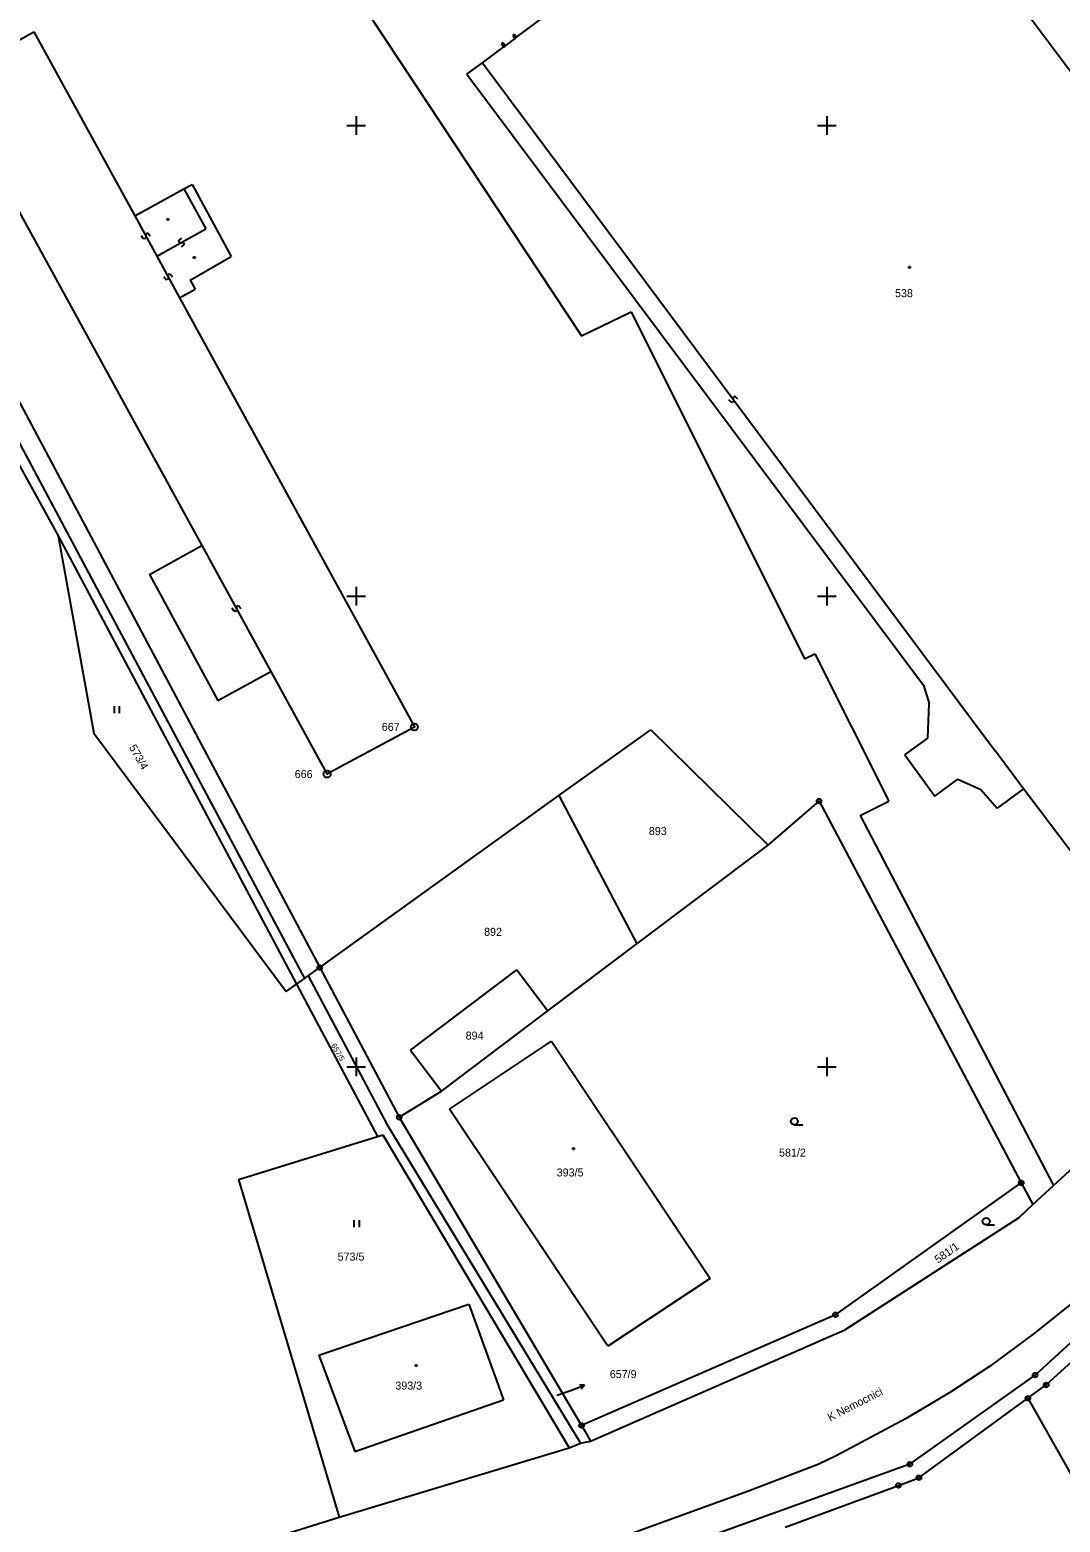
# Model space of a CAD drawing. Extents: x -493648 to -493033, y -1127718 to -1127026.
# Drawn here: x -493284.7 to -493175.2, y -1127598.4 to -1127439.8 of the extents above; entities that cross this region are included whole.
import ezdxf

# ---------------------------------------------------------------- set-up
doc = ezdxf.new("R2010")
doc.units = 0
doc.layers.add('katastrální mapa', color=7, linetype='Continuous')
doc.layers.add('síť', color=7, linetype='Continuous')

msp = doc.modelspace()

# ---------------------------------------------------------------- linework, layer by layer
at = {"layer": 'katastrální mapa'}
for p, q in [((-493232.95, -1127440.62), (-493201.08, -1127416.82)), ((-493254.36, -1127429.53), (-493226.07, -1127472.34)), ((-493182.89, -1127432.48), (-493156.39, -1127468.02)), ((-493293.46, -1127445.19), (-493284.22, -1127440.05)), ((-493284.22, -1127440.05), (-493273.51, -1127459.61)), ((-493233.34, -1127440.42), (-493233.19, -1127440.3)), ((-493233.34, -1127440.42), (-493233.1, -1127440.74)), ((-493233.19, -1127440.3), (-493232.95, -1127440.62)), ((-493233.1, -1127440.74), (-493232.95, -1127440.62)), ((-493236.57, -1127443.33), (-493234.3, -1127441.63)), ((-493234.54, -1127441.31), (-493234.38, -1127441.19)), ((-493234.54, -1127441.31), (-493234.3, -1127441.63)), ((-493234.38, -1127441.19), (-493234.14, -1127441.52)), ((-493234.3, -1127441.63), (-493234.14, -1127441.52)), ((-493234.14, -1127441.52), (-493233.1, -1127440.74)), ((-493238.25, -1127444.56), (-493236.57, -1127443.33)), ((-493236.57, -1127443.33), (-493183.28, -1127514.87)), ((-493293.46, -1127445.19), (-493266.37, -1127494.63)), ((-493238.25, -1127444.56), (-493189.73, -1127509.45)), ((-493268.3, -1127456.72), (-493267.42, -1127456.25)), ((-493267.42, -1127456.25), (-493263.27, -1127463.93)), ((-493273.51, -1127459.61), (-493268.3, -1127456.72)), ((-493268.3, -1127456.72), (-493265.97, -1127460.96)), ((-493273.51, -1127459.61), (-493271.17, -1127463.88)), ((-493271.17, -1127463.88), (-493265.97, -1127460.96)), ((-493270.07, -1127459.91), (-493269.92, -1127459.91)), ((-493270.07, -1127460.06), (-493270.07, -1127459.91)), ((-493269.92, -1127460.06), (-493270.07, -1127460.06)), ((-493269.92, -1127459.91), (-493269.92, -1127460.06)), ((-493272.6, -1127462), (-493272.81, -1127461.72)), ((-493272.46, -1127462.04), (-493272.6, -1127462)), ((-493272.38, -1127461.99), (-493272.46, -1127462.04)), ((-493272.34, -1127461.86), (-493272.38, -1127461.99)), ((-493272.3, -1127461.5), (-493272.34, -1127461.63)), ((-493272.34, -1127461.63), (-493272.34, -1127461.86)), ((-493272.22, -1127461.45), (-493272.3, -1127461.5)), ((-493272.08, -1127461.49), (-493272.22, -1127461.45)), ((-493271.87, -1127461.77), (-493272.08, -1127461.49)), ((-493268.83, -1127462.16), (-493268.87, -1127462.3)), ((-493268.87, -1127462.3), (-493268.82, -1127462.39)), ((-493268.55, -1127461.95), (-493268.83, -1127462.16)), ((-493268.82, -1127462.39), (-493268.68, -1127462.43)), ((-493268.68, -1127462.43), (-493268.46, -1127462.41)), ((-493268.31, -1127462.68), (-493268.59, -1127462.89)), ((-493268.46, -1127462.41), (-493268.32, -1127462.45)), ((-493268.32, -1127462.45), (-493268.27, -1127462.54)), ((-493268.27, -1127462.54), (-493268.31, -1127462.68)), ((-493271.17, -1127463.88), (-493268.75, -1127468.29)), ((-493267.62, -1127466.41), (-493263.27, -1127463.93)), ((-493267.26, -1127463.94), (-493267.11, -1127463.94)), ((-493267.26, -1127464.09), (-493267.26, -1127463.94)), ((-493267.11, -1127464.09), (-493267.26, -1127464.09)), ((-493267.11, -1127463.94), (-493267.11, -1127464.09)), ((-493269.92, -1127465.84), (-493269.96, -1127465.97)), ((-493269.96, -1127465.97), (-493269.96, -1127466.2)), ((-493269.84, -1127465.79), (-493269.92, -1127465.84)), ((-493269.7, -1127465.83), (-493269.84, -1127465.79)), ((-493269.49, -1127466.11), (-493269.7, -1127465.83)), ((-493191.3, -1127464.99), (-493191.15, -1127464.99)), ((-493191.3, -1127465.14), (-493191.3, -1127464.99)), ((-493191.15, -1127465.14), (-493191.3, -1127465.14)), ((-493191.15, -1127464.99), (-493191.15, -1127465.14)), ((-493270.22, -1127466.34), (-493270.43, -1127466.06)), ((-493270.08, -1127466.38), (-493270.22, -1127466.34)), ((-493270, -1127466.33), (-493270.08, -1127466.38)), ((-493269.96, -1127466.2), (-493270, -1127466.33)), ((-493268.75, -1127468.29), (-493267.09, -1127467.38)), ((-493267.62, -1127466.41), (-493267.09, -1127467.38)), ((-493295.49, -1127468.67), (-493281.65, -1127493.57)), ((-493268.75, -1127468.29), (-493243.81, -1127513.86)), ((-493226.07, -1127472.34), (-493220.77, -1127469.79)), ((-493220.77, -1127469.79), (-493202.35, -1127506.66)), ((-493287.7, -1127480.1), (-493255.49, -1127540.62)), ((-493285.95, -1127478.98), (-493253.86, -1127539.45)), ((-493210.15, -1127479.39), (-493210.4, -1127479.14)), ((-493210.01, -1127479.41), (-493210.15, -1127479.39)), ((-493209.93, -1127479.35), (-493210.01, -1127479.41)), ((-493209.92, -1127478.85), (-493209.94, -1127478.99)), ((-493209.94, -1127478.99), (-493209.91, -1127479.21)), ((-493209.91, -1127479.21), (-493209.93, -1127479.35)), ((-493209.84, -1127478.79), (-493209.92, -1127478.85)), ((-493209.7, -1127478.81), (-493209.84, -1127478.79)), ((-493209.45, -1127479.06), (-493209.7, -1127478.81)), ((-493281.65, -1127493.57), (-493277.86, -1127514.55)), ((-493281.65, -1127493.57), (-493256.33, -1127541.22)), ((-493175.91, -1127562.6), (-493102.04, -1127494.48)), ((-493271.96, -1127497.69), (-493266.37, -1127494.63)), ((-493266.37, -1127494.63), (-493259.05, -1127507.99)), ((-493271.96, -1127497.69), (-493264.7, -1127511.08)), ((-493262.97, -1127501.57), (-493263.18, -1127501.28)), ((-493262.83, -1127501.61), (-493262.97, -1127501.57)), ((-493262.75, -1127501.56), (-493262.83, -1127501.61)), ((-493262.71, -1127501.42), (-493262.75, -1127501.56)), ((-493262.67, -1127501.06), (-493262.71, -1127501.2)), ((-493262.71, -1127501.2), (-493262.71, -1127501.42)), ((-493262.59, -1127501.01), (-493262.67, -1127501.06)), ((-493262.45, -1127501.05), (-493262.59, -1127501.01)), ((-493262.24, -1127501.34), (-493262.45, -1127501.05)), ((-493202.35, -1127506.66), (-493201.28, -1127506.13)), ((-493201.28, -1127506.13), (-493193.41, -1127521.77)), ((-493264.7, -1127511.08), (-493259.05, -1127507.99)), ((-493259.05, -1127507.99), (-493253.09, -1127518.87)), ((-493189.73, -1127509.45), (-493189.11, -1127511.39)), ((-493275.68, -1127512.42), (-493275.68, -1127511.67)), ((-493275.18, -1127511.67), (-493275.18, -1127512.42)), ((-493189.28, -1127515.09), (-493189.11, -1127511.39)), ((-493177.87, -1127582.75), (-493098.97, -1127510.41)), ((-493277.86, -1127514.55), (-493257.43, -1127542.01)), ((-493253.09, -1127518.87), (-493243.81, -1127513.86)), ((-493228.45, -1127521.17), (-493218.7, -1127514.18)), ((-493218.7, -1127514.18), (-493206.22, -1127526.45)), ((-493191.72, -1127516.85), (-493189.28, -1127515.09)), ((-493183.28, -1127514.87), (-493182.09, -1127516.46)), ((-493179.09, -1127520.45), (-493182.09, -1127516.46)), ((-493191.72, -1127516.85), (-493188.53, -1127521.23)), ((-493188.53, -1127521.23), (-493186.09, -1127519.45)), ((-493186.09, -1127519.45), (-493183.62, -1127520.54)), ((-493253.86, -1127539.45), (-493228.45, -1127521.17)), ((-493228.45, -1127521.17), (-493220.16, -1127536.92)), ((-493183.62, -1127520.54), (-493181.9, -1127522.52)), ((-493179.09, -1127520.45), (-493181.9, -1127522.52)), ((-493170.1, -1127532.41), (-493179.09, -1127520.45)), ((-493206.22, -1127526.45), (-493200.81, -1127521.76)), ((-493200.81, -1127521.76), (-493179.34, -1127562.32)), ((-493196.45, -1127523.3), (-493193.41, -1127521.77)), ((-493196.45, -1127523.3), (-493175.91, -1127562.6)), ((-493220.16, -1127536.92), (-493206.22, -1127526.45)), ((-493229.64, -1127544.05), (-493220.16, -1127536.92)), ((-493255.49, -1127540.62), (-493255.09, -1127540.33)), ((-493255.09, -1127540.33), (-493253.86, -1127539.45)), ((-493255.09, -1127540.33), (-493246.72, -1127556.1)), ((-493253.86, -1127539.45), (-493245.42, -1127555.36)), ((-493244.22, -1127548.23), (-493232.93, -1127539.7)), ((-493232.93, -1127539.7), (-493229.64, -1127544.05)), ((-493257.43, -1127542.01), (-493256.33, -1127541.22)), ((-493256.33, -1127541.22), (-493255.49, -1127540.62)), ((-493256.33, -1127541.22), (-493248.02, -1127556.85)), ((-493240.93, -1127552.58), (-493229.64, -1127544.05)), ((-493244.22, -1127548.23), (-493240.93, -1127552.58)), ((-493240.09, -1127554.51), (-493229.23, -1127547.28)), ((-493229.23, -1127547.28), (-493212.4, -1127572.49)), ((-493245.42, -1127555.36), (-493240.93, -1127552.58)), ((-493223.25, -1127579.68), (-493240.09, -1127554.51)), ((-493246.72, -1127556.1), (-493226.17, -1127589.97)), ((-493245.42, -1127555.36), (-493226.05, -1127588.09)), ((-493203.44, -1127556.16), (-493202.56, -1127556.16)), ((-493262.48, -1127561.98), (-493247.72, -1127557.41)), ((-493248.02, -1127556.85), (-493247.72, -1127557.41)), ((-493247.72, -1127557.41), (-493247.15, -1127557.23)), ((-493247.15, -1127557.23), (-493227.38, -1127590.46)), ((-493226.97, -1127558.61), (-493226.82, -1127558.61)), ((-493226.97, -1127558.76), (-493226.97, -1127558.61)), ((-493226.82, -1127558.76), (-493226.97, -1127558.76)), ((-493226.82, -1127558.61), (-493226.82, -1127558.76)), ((-493262.48, -1127561.98), (-493251.78, -1127597.83)), ((-493199.08, -1127576.34), (-493179.34, -1127562.32)), ((-493179.34, -1127562.32), (-493178.11, -1127564.63)), ((-493178.11, -1127564.63), (-493175.91, -1127562.6)), ((-493179.58, -1127565.99), (-493178.11, -1127564.63)), ((-493250.19, -1127567.02), (-493250.19, -1127566.27)), ((-493249.69, -1127566.27), (-493249.69, -1127567.02)), ((-493198.08, -1127577.92), (-493179.58, -1127565.99)), ((-493183.07, -1127566.78), (-493182.19, -1127566.78)), ((-493212.4, -1127572.49), (-493223.25, -1127579.68)), ((-493253.96, -1127580.61), (-493238.02, -1127575.22)), ((-493238.02, -1127575.22), (-493234.34, -1127585.37)), ((-493199.08, -1127576.34), (-493226.05, -1127588.09)), ((-493176.68, -1127583.78), (-493167.56, -1127575.44)), ((-493225.09, -1127589.75), (-493198.08, -1127577.92)), ((-493253.96, -1127580.61), (-493250.14, -1127590.86)), ((-493243.69, -1127581.64), (-493243.54, -1127581.64)), ((-493243.69, -1127581.79), (-493243.69, -1127581.64)), ((-493243.54, -1127581.64), (-493243.54, -1127581.79)), ((-493243.54, -1127581.79), (-493243.69, -1127581.79)), ((-493191.17, -1127592.22), (-493177.87, -1127582.75)), ((-493228.63, -1127584.88), (-493227.13, -1127584.34)), ((-493227.13, -1127584.34), (-493225.72, -1127583.83)), ((-493225.72, -1127583.83), (-493226.27, -1127583.76)), ((-493225.72, -1127583.83), (-493226.1, -1127584.24)), ((-493178.63, -1127585.2), (-493176.68, -1127583.78)), ((-493250.14, -1127590.86), (-493234.34, -1127585.37)), ((-493190.21, -1127593.65), (-493178.63, -1127585.2)), ((-493178.63, -1127585.2), (-493150.81, -1127634.64)), ((-493226.05, -1127588.09), (-493225.68, -1127588.72)), ((-493225.68, -1127588.72), (-493225.09, -1127589.75)), ((-493251.78, -1127597.83), (-493227.38, -1127590.46)), ((-493227.38, -1127590.46), (-493226.17, -1127589.97)), ((-493226.17, -1127589.97), (-493225.09, -1127589.75)), ((-493191.17, -1127592.22), (-493216.38, -1127601.32)), ((-493192.39, -1127594.46), (-493190.21, -1127593.65)), ((-493204.41, -1127598.9), (-493192.39, -1127594.46)), ((-493285.34, -1127608.28), (-493251.78, -1127597.83))]:
    msp.add_line(p, q, dxfattribs=at)
msp.add_lwpolyline([(-493097.31, -1127505.21), (-493098.12, -1127505.44), (-493098.98, -1127505.84), (-493107.13, -1127513.2), (-493127.98, -1127533.26), (-493136.84, -1127541.39), (-493149.38, -1127552.86), (-493159.12, -1127561.82), (-493168.03, -1127569.78), (-493174.01, -1127575.14), (-493177.93, -1127578.28), (-493182.72, -1127581.82), (-493186.93, -1127584.59), (-493191.56, -1127587.36), (-493199.02, -1127591.33), (-493200.84, -1127592.19), (-493208.3, -1127595.08), (-493221.5, -1127599.86), (-493230.41, -1127602.91), (-493259.01, -1127611.75), (-493280.04, -1127618.2), (-493281.66, -1127619.38), (-493281.8, -1127619.61)], dxfattribs=at)
for centre, radius in [((-493243.81, -1127513.89), 0.375), ((-493243.81, -1127513.89), 0.005), ((-493253.08, -1127518.9), 0.375), ((-493253.08, -1127518.9), 0.005), ((-493200.81, -1127521.76), 0.25), ((-493200.81, -1127521.76), 0.005), ((-493253.86, -1127539.45), 0.25), ((-493253.86, -1127539.45), 0.005), ((-493245.42, -1127555.36), 0.25), ((-493245.42, -1127555.36), 0.005), ((-493203.44, -1127555.785), 0.375), ((-493179.34, -1127562.32), 0.25), ((-493179.34, -1127562.32), 0.005), ((-493183.07, -1127566.405), 0.375), ((-493199.08, -1127576.34), 0.25), ((-493199.08, -1127576.34), 0.005), ((-493177.87, -1127582.75), 0.25), ((-493177.87, -1127582.75), 0.005), ((-493176.68, -1127583.78), 0.25), ((-493176.68, -1127583.78), 0.005), ((-493178.63, -1127585.2), 0.25), ((-493178.63, -1127585.2), 0.005), ((-493226.05, -1127588.09), 0.25), ((-493226.05, -1127588.09), 0.005), ((-493191.17, -1127592.22), 0.25), ((-493191.17, -1127592.22), 0.005), ((-493192.39, -1127594.46), 0.25), ((-493190.21, -1127593.65), 0.25), ((-493190.21, -1127593.65), 0.005), ((-493192.39, -1127594.46), 0.005)]:
    msp.add_circle(centre, radius, dxfattribs=at)
at = {"layer": 'síť'}
for p, q in [((-493251, -1127450), (-493249, -1127450)), ((-493250, -1127449), (-493250, -1127451)), ((-493201, -1127450), (-493199, -1127450)), ((-493200, -1127449), (-493200, -1127451)), ((-493250, -1127499), (-493250, -1127501)), ((-493200, -1127499), (-493200, -1127501)), ((-493251, -1127500), (-493249, -1127500)), ((-493201, -1127500), (-493199, -1127500)), ((-493251, -1127550), (-493249, -1127550)), ((-493250, -1127549), (-493250, -1127551)), ((-493201, -1127550), (-493199, -1127550)), ((-493200, -1127549), (-493200, -1127551))]:
    msp.add_line(p, q, dxfattribs=at)

# ---------------------------------------------------------------- texts
at = {"layer": 'katastrální mapa'}
for s, height, p in [('538', 0.849996, (-493192.75, -1127468.23)), ('667', 0.849996, (-493247.27, -1127514.31)), ('666', 0.849996, (-493256.52, -1127519.32)), ('893', 0.849996, (-493218.9, -1127525.37)), ('892', 0.849996, (-493236.4, -1127536.08)), ('894', 0.849996, (-493238.36, -1127547.1)), ('581/2', 0.849996, (-493205.07, -1127559.53)), ('393/5', 0.849996, (-493228.69, -1127561.64)), ('573/5', 0.849996, (-493251.96, -1127570.58)), ('657/9', 0.849996, (-493223.05, -1127583.06)), ('393/3', 0.849996, (-493245.83, -1127584.28)), ('657/9', 0.049998, (-493228.74, -1127584.88))]:
    msp.add_text(s, height=height, dxfattribs=at).set_placement(p)
for s, height, rotation, p in [('573/4', 0.849996, 299.772, (-493274.16, -1127516.06)), ('657/5', 0.599994, 300.0599972, (-493252.69, -1127547.72)), ('581/1', 0.849996, 35.298, (-493188.18, -1127570.91)), ('K Nemocnici', 0.849996, 27, (-493199.65, -1127587.67))]:
    msp.add_text(s, height=height, rotation=rotation, dxfattribs=at).set_placement(p)

doc.saveas('drawing.dxf')
